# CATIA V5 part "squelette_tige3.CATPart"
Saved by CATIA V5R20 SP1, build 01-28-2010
Part number: squelette_tige3
Publications: "Droite.1", "Droite.3", "Plan.2"
Bounding box of the stored display mesh (mm): x -139209 to 2.268, y -88.581 to 9862240, z -1647735 to 42.003
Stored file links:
  C:\Users\Fox\Desktop\IAO Projet\A RENDRE\Sauvegarde IFMA\squelette_tige3.CATPart
  C:\Users\Fox\Desktop\IAO Projet\A RENDRE\Sauvegarde IFMA\squelette.CATProduct
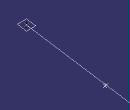
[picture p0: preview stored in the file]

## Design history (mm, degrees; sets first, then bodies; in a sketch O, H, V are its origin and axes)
Set1
  Line1: type PtPt, FirstPoint Point1, SecondPoint Point3
  Line2: type Normal, RefPoint Point1, RefSkin Plane2, Start -10, End 10
  Plane1: type Normal, Curve Line2, RefPoint Point1
Set2
  Point1: linked copy from another document
  Line3: linked copy from another document
  Point2: linked copy from another document
  Plane2: linked copy from another document
  Point3: linked copy from another document
Body1 (main body)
